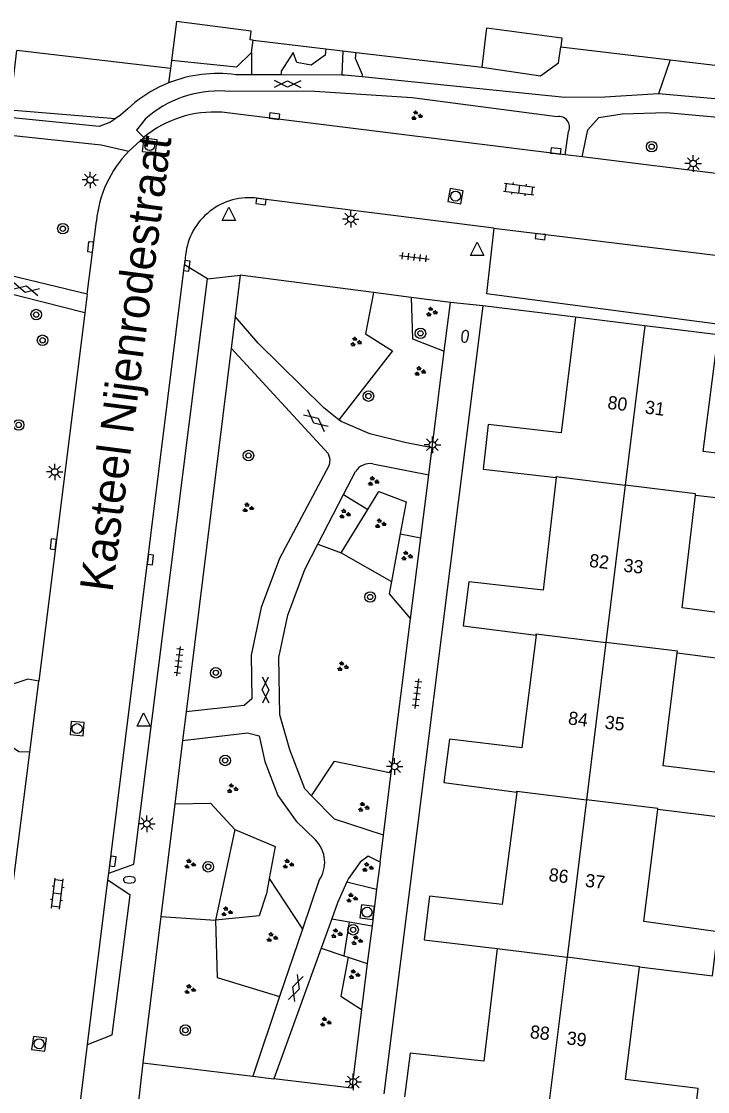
# Model space of a CAD drawing. Extents: x 131000 to 133014, y 396499 to 399001.
# Drawn here: x 131362.8 to 131414.8, y 396865 to 396946.2 of the extents above; entities that cross this region are included whole.
import ezdxf

# ---------------------------------------------------------------- set-up
doc = ezdxf.new("R2010")
doc.units = 0
for name, color, linetype in [('gg-afsc-erfafscheiding', 7, 'Continuous'), ('gg-afsc-muur', 7, 'Continuous'), ('gg-anno-huisnummerreeks BGT', 7, 'Continuous'), ('gg-anno-openbare ruimte label', 7, 'Continuous'), ('gg-bbg-hoofdgebouw', 7, 'Continuous'), ('gg-bbg-tussenscheiding', 7, 'Continuous'), ('gg-knt-verharding', 7, 'Continuous'), ('gg-knt-verharding nz', 7, 'Continuous'), ('gt-grn-groengrens', 7, 'Continuous'), ('gt-grn-weggrens', 7, 'Continuous'), ('gt-symb-boom', 7, 'Continuous'), ('gt-symb-brandkraan', 7, 'Continuous'), ('gt-symb-gesloten verharding', 7, 'Continuous'), ('gt-symb-groenvak', 7, 'Continuous'), ('gt-symb-klinker verharding', 7, 'Continuous'), ('gt-symb-kolk', 7, 'Continuous'), ('gt-symb-lichtmast', 7, 'Continuous'), ('gt-symb-rioolschacht', 7, 'Continuous'), ('gt-symb-tegel verharding', 7, 'Continuous'), ('gt-symb-waterafsluiter', 7, 'Continuous')]:
    doc.layers.add(name, color=color, linetype=linetype)

# ---------------------------------------------------------------- blocks, each defined once
blk = doc.blocks.new('gt0-GRVAK')
at = {"layer": 'gt-symb-groenvak'}
for p, q in [((-0.11, 0.189), (-0.228, 0.24)), ((-0.182, 0.153), (0.088, 0.153)), ((-0.091, 0.211), (-0.156, 0.322)), ((-0.047, 0.214), (-0.047, 0.393)), ((-0.004, 0.211), (0.061, 0.322)), ((0.015, 0.189), (0.133, 0.24)), ((0.262, -0.052), (0.197, 0.059)), ((0.305, -0.049), (0.305, 0.13)), ((0.349, -0.052), (0.414, 0.059)), ((-0.245, -0.228), (-0.363, -0.177)), ((-0.318, -0.264), (-0.047, -0.264)), ((-0.226, -0.206), (-0.291, -0.095)), ((-0.183, -0.203), (-0.183, -0.024)), ((-0.139, -0.206), (-0.074, -0.095)), ((-0.12, -0.228), (-0.002, -0.177)), ((0.243, -0.074), (0.125, -0.023)), ((0.17, -0.11), (0.441, -0.11)), ((0.368, -0.074), (0.486, -0.023))]:
    blk.add_line(p, q, dxfattribs=at)
blk = doc.blocks.new('gt0-BOOM')
at = {"layer": 'gt-symb-boom'}
for radius in [0.4, 0.2]:
    blk.add_circle((0, 0), radius, dxfattribs=at)
blk = doc.blocks.new('gt0-RS')
at = {"layer": 'gt-symb-rioolschacht'}
blk.add_lwpolyline([(-0.5, -0.5), (0.5, -0.5), (0.5, 0.5), (-0.5, 0.5)], close=True, dxfattribs=at)
blk.add_circle((0, 0), 0.375, dxfattribs=at)
blk = doc.blocks.new('gt0-LMAST')
at = {"layer": 'gt-symb-lichtmast'}
for p, q in [((-0.182, 0.173), (-0.447, 0.438)), ((-0.005, 0.246), (-0.005, 0.621)), ((0.172, 0.173), (0.437, 0.438)), ((-0.255, -0.004), (-0.63, -0.004)), ((-0.182, -0.181), (-0.447, -0.446)), ((-0.005, -0.254), (-0.005, -0.629)), ((0.437, -0.446), (0.172, -0.181)), ((0.245, -0.004), (0.62, -0.004))]:
    blk.add_line(p, q, dxfattribs=at)
blk.add_circle((-0.005, -0.004), 0.25, dxfattribs=at)
blk = doc.blocks.new('gt0-GESVH1')
at = {"layer": 'gt-symb-gesloten verharding'}
for p, q in [((-0.992, -0.261), (0.008, 0.239)), ((0.008, -0.261), (-0.992, 0.239)), ((0.008, 0.239), (1.008, -0.261)), ((1.008, 0.239), (0.008, -0.261))]:
    blk.add_line(p, q, dxfattribs=at)
blk = doc.blocks.new('gt0-KL1')
at = {"layer": 'gt-symb-klinker verharding'}
for p, q in [((-1.15, 0.3), (1.15, 0.3)), ((-1, -0.3), (-1, 0.3)), ((-0.5, 0.3), (-0.5, 0.45)), ((0, -0.3), (0, 0.3)), ((0.5, 0.3), (0.5, 0.45)), ((1, -0.3), (1, 0.3)), ((-1.15, -0.3), (1.15, -0.3)), ((-0.5, -0.45), (-0.5, -0.3)), ((0.5, -0.45), (0.5, -0.3))]:
    blk.add_line(p, q, dxfattribs=at)
blk = doc.blocks.new('gt0-KOLK')
at = {"layer": 'gt-symb-kolk'}
blk.add_lwpolyline([(0, 0), (0.375, 0), (0.375, 0.4), (-0.375, 0.4), (-0.375, 0), (0, 0)], dxfattribs=at)
blk = doc.blocks.new('gt0-BR')
at = {"layer": 'gt-symb-brandkraan'}
for centre, radius, start, end in [((-0.244, 0), 0.206, 107.56694, 252.43307), ((0.599, -2.664), 3, 106.89205, 107.56694), ((0, -0.691), 0.938, 73.10799, 106.89205), ((-0.599, -2.664), 3, 72.43309, 73.10799), ((0.244, 0), 0.206, 287.56695, 72.43309), ((0.599, 2.664), 3, 252.43307, 253.10797), ((0, 0.691), 0.938, 253.10797, 286.89206), ((-0.599, 2.664), 3, 286.89206, 287.56695)]:
    blk.add_arc(centre, radius, start, end, dxfattribs=at)
blk = doc.blocks.new('gt0-TEG1')
at = {"layer": 'gt-symb-tegel verharding'}
for p, q in [((-1.125, 0), (1.125, 0)), ((-0.9, -0.25), (-0.9, 0.25)), ((-0.45, -0.25), (-0.45, 0.25)), ((0, -0.25), (0, 0.25)), ((0.45, -0.25), (0.45, 0.25)), ((0.9, -0.25), (0.9, 0.25))]:
    blk.add_line(p, q, dxfattribs=at)
blk = doc.blocks.new('gt0-WAFSL')
at = {"layer": 'gt-symb-waterafsluiter'}
for p, q in [((-0.5, -0.333), (0, 0.667)), ((0, 0.667), (0.5, -0.333)), ((0.5, -0.333), (-0.5, -0.333))]:
    blk.add_line(p, q, dxfattribs=at)

msp = doc.modelspace()

# ---------------------------------------------------------------- linework, layer by layer
at = {"layer": 'gg-afsc-erfafscheiding'}
msp.add_line((131397.74, 396924.6), (131390.25, 396864.87), dxfattribs=at)
at = {"layer": 'gg-afsc-muur'}
for p, q in [((131380.233, 396943.794), (131380.344, 396944.733)), ((131404.77, 396923.73), (131397.74, 396924.6))]:
    msp.add_line(p, q, dxfattribs=at)
msp.add_lwpolyline([(131380.233, 396943.794), (131379.075, 396942.691), (131374.161, 396943.192)], dxfattribs=at)
at = {"layer": 'gg-bbg-hoofdgebouw'}
for p, q in [((131380.344, 396944.733), (131385.865, 396944.076)), ((131403.65, 396944.22), (131411.945, 396943.227)), ((131374.08, 396942.58), (131362.444, 396943.935)), ((131385.865, 396944.076), (131387.143, 396943.924)), ((131387.143, 396943.924), (131388.152, 396943.804)), ((131388.152, 396943.804), (131397.69, 396942.67)), ((131374.161, 396943.192), (131374.08, 396942.58)), ((131411.945, 396943.227), (131434.011, 396940.586)), ((131410.02, 396923.079), (131404.77, 396923.73)), ((131415.57, 396922.39), (131410.02, 396923.079))]:
    msp.add_line(p, q, dxfattribs=at)
for points in [[(131380.344, 396944.733), (131380.12, 396944.76), (131380.2, 396945.42), (131374.55, 396946.15), (131374.161, 396943.192)], [(131397.69, 396942.67), (131398.04, 396945.66), (131403.74, 396944.91), (131403.65, 396944.22)], [(131404.77, 396923.73), (131403.67, 396914.96), (131398.14, 396915.59), (131397.76, 396912.22), (131403.29, 396911.59)], [(131413.85, 396910.25), (131419.61, 396909.58), (131419.99, 396912.88), (131414.43, 396913.55), (131415.57, 396922.39)], [(131403.29, 396911.59), (131402.32, 396903.05), (131396.68, 396903.67), (131396.26, 396900.34), (131401.78, 396899.63)], [(131412.47, 396898.29), (131419.498, 396897.396), (131419.948, 396900.756), (131412.85, 396901.71), (131413.85, 396910.25)], [(131401.78, 396899.63), (131400.69, 396891.1), (131395.22, 396891.76), (131394.8, 396888.46), (131400.32, 396887.74)], [(131411, 396886.45), (131417.961, 396885.591), (131418.371, 396888.871), (131411.4, 396889.73), (131412.47, 396898.29)], [(131400.32, 396887.74), (131399.21, 396879.22), (131393.7, 396879.86), (131393.3, 396876.55), (131398.84, 396875.89)], [(131409.6, 396874.5), (131415.13, 396873.81), (131415.54, 396877.16), (131409.94, 396877.92), (131411, 396886.45)], [(131398.84, 396875.89), (131397.82, 396867.35), (131392.25, 396867.95), (131391.81, 396864.65)], [(131413.67, 396861.96), (131414.06, 396865.28), (131408.54, 396865.96), (131409.6, 396874.5)]]:
    msp.add_lwpolyline(points, dxfattribs=at)
at = {"layer": 'gg-bbg-tussenscheiding'}
for p, q in [((131410.02, 396923.079), (131408.531, 396911.003)), ((131408.531, 396911.003), (131407.061, 396899.082)), ((131407.061, 396899.082), (131405.591, 396887.161)), ((131405.591, 396887.161), (131404.122, 396875.241)), ((131398.84, 396875.89), (131404.122, 396875.241)), ((131404.122, 396875.241), (131402.651, 396863.316)), ((131409.6, 396874.5), (131404.122, 396875.241))]:
    msp.add_line(p, q, dxfattribs=at)
for points in [[(131403.29, 396911.59), (131403.297, 396911.652), (131408.531, 396911.003)], [(131413.85, 396910.25), (131413.861, 396910.343), (131408.531, 396911.003)], [(131401.78, 396899.63), (131401.794, 396899.738), (131407.061, 396899.082)], [(131412.47, 396898.29), (131412.485, 396898.41), (131407.061, 396899.082)], [(131400.32, 396887.74), (131400.33, 396887.818), (131405.591, 396887.161)], [(131411, 396886.45), (131411.005, 396886.491), (131405.591, 396887.161)]]:
    msp.add_lwpolyline(points, dxfattribs=at)
at = {"layer": 'gg-knt-verharding'}
for p, q in [((131380.226, 396942.101), (131379.032, 396942.105)), ((131382.464, 396942.092), (131380.226, 396942.101)), ((131387.072, 396942.074), (131382.464, 396942.092)), ((131371.393, 396939.996), (131370.863, 396939.534)), ((131403.994, 396936.038), (131377.97, 396939.26)), ((131403.994, 396936.038), (131404.233, 396937.816)), ((131370.921, 396936.317), (131372.054, 396937.35)), ((131405.272, 396935.88), (131403.994, 396936.038)), ((131426.19, 396933.29), (131405.272, 396935.88)), ((131398.589, 396930.485), (131380.7, 396932.74)), ((131367.778, 396925.486), (131368.47, 396931.01)), ((131375.23, 396928.47), (131375.136, 396927.713)), ((131367.778, 396925.486), (131359.668, 396927.433)), ((131376.884, 396926.642), (131375.136, 396927.713)), ((131379.37, 396926.91), (131378.981, 396923.774)), ((131389.452, 396925.605), (131379.37, 396926.91)), ((131392.313, 396925.235), (131389.452, 396925.605)), ((131367.778, 396925.486), (131367.601, 396924.07)), ((131395.29, 396924.85), (131392.313, 396925.235)), ((131394.825, 396921.155), (131395.29, 396924.85)), ((131367.601, 396924.07), (131364.11, 396896.15)), ((131378.981, 396923.774), (131378.686, 396921.387)), ((131378.686, 396921.387), (131375.275, 396893.83)), ((131393.905, 396913.841), (131394.825, 396921.155)), ((131393.647, 396911.791), (131393.905, 396913.841)), ((131389.416, 396912.609), (131393.647, 396911.791)), ((131387.202, 396910.296), (131388.104, 396912.045)), ((131393.046, 396907.009), (131393.647, 396911.791)), ((131385.259, 396906.527), (131387.202, 396910.296)), ((131392.274, 396900.862), (131393.046, 396907.009)), ((131390.808, 396889.195), (131392.274, 396900.862)), ((131363.43, 396890.77), (131364.11, 396896.15)), ((131375.275, 396893.83), (131375.005, 396891.647)), ((131375.005, 396891.647), (131374.412, 396886.855)), ((131362.09, 396880.2), (131363.43, 396890.77)), ((131390.214, 396884.464), (131390.808, 396889.195)), ((131374.412, 396886.855), (131373.354, 396878.307)), ((131389.957, 396882.417), (131390.214, 396884.464)), ((131389.957, 396882.417), (131389.702, 396880.387)), ((131369.342, 396881.053), (131369.409, 396881.599)), ((131385.321, 396881.025), (131384.082, 396877.36)), ((131389.702, 396880.387), (131389.353, 396877.601)), ((131373.354, 396878.307), (131371.98, 396867.21)), ((131386.297, 396878.141), (131385.492, 396875.911)), ((131384.082, 396877.36), (131382.352, 396872.24)), ((131389.353, 396877.601), (131388.994, 396874.744)), ((131385.492, 396875.911), (131381.917, 396866.016)), ((131388.994, 396874.744), (131388.557, 396871.26)), ((131382.352, 396872.24), (131380.314, 396866.209)), ((131367.182, 396863.652), (131367.798, 396868.619)), ((131371.98, 396867.21), (131380.314, 396866.209)), ((131380.314, 396866.209), (131381.917, 396866.016))]:
    msp.add_line(p, q, dxfattribs=at)
for points in [[(131388.609, 396941.937), (131387.274, 396942.073), (131387.072, 396942.074)], [(131411.056, 396940.651), (131406.99, 396940.417), (131403.963, 396940.371), (131388.609, 396941.937)], [(131369.895, 396938.757), (131369.539, 396938.506), (131368.672, 396938.178), (131353.225, 396939.729), (131352.687, 396940.084), (131352.853, 396941.597)], [(131403.371, 396938.924), (131392.404, 396940.363), (131385.022, 396940.826), (131378.208, 396940.867)], [(131434.85, 396935.52), (131432.32, 396936.8), (131429.42, 396937.84), (131426.61, 396939.02), (131416.488, 396940.17), (131411.056, 396940.651)], [(131370.863, 396939.534), (131370.297, 396939.041), (131369.895, 396938.757)], [(131372.174, 396938.751), (131371.517, 396937.895), (131372.054, 396937.35)], [(131405.272, 396935.88), (131405.693, 396937.924), (131406.529, 396938.865), (131408.295, 396939.153), (131411.669, 396939.237), (131418.309, 396938.638), (131427.28, 396937.29), (131429.46, 396936.29)], [(131354.124, 396938.36), (131368.833, 396936.794), (131370.921, 396936.317)], [(131398.589, 396930.485), (131398.034, 396925.522), (131422.031, 396922.362)], [(131369.409, 396881.599), (131371.301, 396882.265), (131376.884, 396926.642)], [(131367.601, 396924.07), (131359.423, 396926.139), (131358.724, 396925.796), (131358.24, 396925.233), (131357.965, 396923.398), (131358.063, 396921.848), (131358.695, 396919.777), (131359.499, 396917.976)], [(131386.843, 396915.958), (131385.707, 396916.873), (131380.732, 396921.773), (131378.981, 396923.774)], [(131378.686, 396921.387), (131386.036, 396913.406), (131386.144, 396912.977), (131386.099, 396912.505), (131382.341, 396905.449), (131380.958, 396901.732), (131380.192, 396898.121), (131380.258, 396894.817), (131379.674, 396894.308), (131375.275, 396893.83)], [(131393.905, 396913.841), (131391.848, 396914.238), (131389.176, 396914.895), (131387.002, 396915.83), (131386.843, 396915.958)], [(131384.761, 396887.468), (131384.269, 396887.976), (131383.129, 396890.945), (131382.366, 396893.583), (131382.298, 396897.93), (131382.98, 396901.145), (131384.265, 396904.599), (131385.259, 396906.527)], [(131364.11, 396896.15), (131363.27, 396896.3), (131361.39, 396895.67), (131352.1, 396896.827)], [(131363.43, 396890.77), (131362.61, 396890.8), (131361.16, 396891.78)], [(131375.005, 396891.647), (131379.919, 396892.223), (131380.8, 396892.005), (131381.241, 396890.063), (131382.213, 396887.488), (131383.598, 396885.531), (131385.073, 396884.11)], [(131390.214, 396884.464), (131386.497, 396885.676), (131384.761, 396887.468)], [(131389.957, 396882.417), (131389.051, 396882.878), (131388.453, 396882.433), (131387.57, 396881.195), (131387.452, 396880.935)], [(131367.798, 396868.619), (131369.68, 396869.343), (131371.027, 396879.917), (131369.342, 396881.053)], [(131387.452, 396880.935), (131386.731, 396879.341), (131386.297, 396878.141)], [(131388.557, 396871.26), (131387.81, 396865.31), (131381.917, 396866.016)]]:
    msp.add_lwpolyline(points, dxfattribs=at)
for centre, radius, start, end in [((131377.651, 396932.222), 9.979, 82.04276, 111.85288), ((131377.65, 396932.219), 9.982, 111.84641, 128.82044), ((131377.774, 396932.443), 8.435, 87.05183, 131.59762), ((131377.384, 396930.956), 8.324, 85.9666, 129.81909), ((131403.526, 396938.155), 0.784, 334.34494, 101.41934), ((131377.318, 396930.143), 8.891, 136.01752, 174.40345), ((131380.05, 396927.934), 4.85, 82.29884, 173.65389), ((131389.174, 396911.363), 1.269, 79.02227, 147.50135), ((131383.366, 396882.42), 2.402, 324.49146, 44.70067)]:
    msp.add_arc(centre, radius, start, end, dxfattribs=at)
at = {"layer": 'gg-knt-verharding nz'}
for p, q in [((131398.589, 396930.485), (131422.755, 396927.538)), ((131369.409, 396881.599), (131375.136, 396927.713)), ((131367.798, 396868.619), (131369.342, 396881.053))]:
    msp.add_line(p, q, dxfattribs=at)
at = {"layer": 'gt-grn-groengrens'}
for p, q in [((131380.233, 396943.794), (131380.226, 396942.101)), ((131387.143, 396943.924), (131387.072, 396942.074)), ((131411.945, 396943.227), (131411.056, 396940.651)), ((131374.08, 396942.58), (131373.936, 396941.484)), ((131387.202, 396910.296), (131389.041, 396909.165)), ((131387.025, 396905.865), (131389.041, 396909.165)), ((131391.487, 396907.302), (131390.822, 396903.713)), ((131391.487, 396907.302), (131393.046, 396907.009)), ((131385.259, 396906.527), (131387.025, 396905.865)), ((131387.025, 396905.865), (131390.822, 396903.713)), ((131378.956, 396884.901), (131377.504, 396878.034)), ((131381.57, 396881.181), (131384.082, 396877.36)), ((131387.452, 396880.935), (131389.702, 396880.387)), ((131373.354, 396878.307), (131377.504, 396878.034)), ((131386.297, 396878.141), (131387.627, 396877.906)), ((131387.627, 396877.906), (131387.21, 396875.338)), ((131387.627, 396877.906), (131389.353, 396877.601)), ((131385.492, 396875.911), (131387.21, 396875.338)), ((131387.21, 396875.338), (131387.547, 396875.226)), ((131387.547, 396875.226), (131388.994, 396874.744))]:
    msp.add_line(p, q, dxfattribs=at)
for points in [[(131397.69, 396942.67), (131402.106, 396942.029), (131403.486, 396943.002), (131403.65, 396944.22)], [(131369.895, 396938.757), (131361.918, 396939.42), (131362.444, 396943.935)], [(131385.865, 396944.076), (131385.806, 396943.58), (131384.746, 396942.835), (131383.646, 396943.044), (131383.385, 396943.792), (131382.465, 396942.37), (131382.464, 396942.092)], [(131388.609, 396941.937), (131388.627, 396942.113), (131388.097, 396943.341), (131388.152, 396943.804)], [(131389.452, 396925.605), (131388.849, 396922.481), (131390.895, 396921.179), (131386.843, 396915.958)], [(131392.313, 396925.235), (131392.423, 396922.089), (131394.825, 396921.155)], [(131389.041, 396909.165), (131389.87, 396910.521), (131391.939, 396909.745), (131391.487, 396907.302)], [(131390.822, 396903.713), (131390.646, 396902.762), (131392.274, 396900.862)], [(131384.761, 396887.468), (131386.508, 396890.088), (131390.808, 396889.195)], [(131374.412, 396886.855), (131377.113, 396886.911), (131378.956, 396884.901)], [(131378.956, 396884.901), (131382.027, 396883.617), (131381.57, 396881.181)], [(131381.57, 396881.181), (131381.357, 396880.044), (131380.798, 396878.369), (131377.504, 396878.034)], [(131377.504, 396878.034), (131377.616, 396873.679), (131382.352, 396872.24)], [(131387.547, 396875.226), (131386.996, 396872.283), (131388.557, 396871.26)]]:
    msp.add_lwpolyline(points, dxfattribs=at)
at = {"layer": 'gt-grn-weggrens'}
for p, q in [((131376.884, 396926.642), (131379.37, 396926.91)), ((131397.74, 396924.6), (131395.29, 396924.85)), ((131371.98, 396867.21), (131371.64, 396864.1))]:
    msp.add_line(p, q, dxfattribs=at)

# ---------------------------------------------------------------- block references
at = {"layer": 'gt-symb-boom'}
for p in [(131410.535, 396936.656), (131365.935, 396930.439), (131363.916, 396923.928), (131364.398, 396921.983), (131393.019, 396922.507), (131389.078, 396917.753), (131362.587, 396915.564), (131379.992, 396913.247), (131389.208, 396902.524), (131377.518, 396896.781), (131378.227, 396890.139), (131376.948, 396882.083), (131387.919, 396877.305), (131375.213, 396869.694)]:
    msp.add_blockref('gt0-BOOM', p, dxfattribs=at)
at = {"layer": 'gt-symb-brandkraan', "rotation": 80.6789392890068}
msp.add_blockref('gt0-BR', (131396.4, 396922.285), dxfattribs=at)
at = {"layer": 'gt-symb-brandkraan'}
msp.add_blockref('gt0-BR', (131370.978, 396881.092), dxfattribs=at)
at = {"layer": 'gt-symb-gesloten verharding'}
for p, rotation in [((131382.962, 396941.394), 179.7708181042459), ((131363.125, 396925.872), -13.48012621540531), ((131385.103, 396915.909), -39.196688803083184), ((131381.277, 396895.474), 90.9166542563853), ((131383.574, 396872.887), 71.3294165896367)]:
    msp.add_blockref('gt0-GESVH1', p, dxfattribs=dict(at, rotation=rotation))
at = {"layer": 'gt-symb-groenvak'}
for p in [(131392.72, 396939.005), (131393.85, 396924.127), (131388.104, 396921.855), (131392.962, 396919.626), (131389.428, 396911.289), (131379.934, 396909.285), (131387.27, 396908.813), (131389.967, 396908.082), (131391.966, 396905.638), (131387.111, 396897.253), (131378.757, 396888.004), (131388.685, 396886.592), (131375.536, 396882.281), (131382.977, 396882.281), (131389.004, 396882.033), (131387.805, 396879.7), (131378.333, 396878.668), (131381.755, 396876.725), (131386.645, 396877.015), (131388.186, 396876.489), (131387.987, 396873.913), (131375.536, 396872.78), (131385.805, 396870.302)]:
    msp.add_blockref('gt0-GRVAK', p, dxfattribs=at)
at = {"layer": 'gt-symb-klinker verharding'}
for p, rotation in [((131400.5, 396933.438), -7.125016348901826), ((131365.516, 396880.05), 82.8749836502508)]:
    msp.add_blockref('gt0-KL1', p, dxfattribs=dict(at, rotation=rotation))
at = {"layer": 'gt-symb-kolk'}
for p, rotation in [((131381.938, 396938.77), -7.068140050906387), ((131403.249, 396936.13), -7.068140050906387), ((131380.973, 396932.698), 171.3757712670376), ((131402.128, 396930.036), 172.87498364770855), ((131368.223, 396929.037), 84.20389934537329), ((131375.128, 396927.654), -97.23872650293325), ((131365.404, 396906.502), 82.80691860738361), ((131372.362, 396905.376), -97.29556014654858), ((131369.519, 396882.518), -97.46597406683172)]:
    msp.add_blockref('gt0-KOLK', p, dxfattribs=dict(at, rotation=rotation))
at = {"layer": 'gt-symb-lichtmast'}
for p in [(131413.685, 396935.379), (131368.019, 396934.137), (131387.743, 396931.171), (131393.932, 396914.068), (131365.318, 396912.006), (131391.071, 396889.679), (131372.307, 396885.339), (131387.938, 396865.779)]:
    msp.add_blockref('gt0-LMAST', p, dxfattribs=at)
at = {"layer": 'gt-symb-rioolschacht'}
for p, rotation in [((131372.506, 396936.735), 82.87498365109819), ((131395.68, 396932.907), -9.556527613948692), ((131367.015, 396892.554), 85.1221191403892), ((131388.978, 396878.638), -7.004259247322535), ((131364.133, 396868.664), 82.00768607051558)]:
    msp.add_blockref('gt0-RS', p, dxfattribs=dict(at, rotation=rotation))
at = {"layer": 'gt-symb-tegel verharding'}
for p, rotation in [((131392.555, 396928.279), -7.125016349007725), ((131374.716, 396897.664), 82.99574075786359), ((131392.758, 396895.201), 82.99574075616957)]:
    msp.add_blockref('gt0-TEG1', p, dxfattribs=dict(at, rotation=rotation))
at = {"layer": 'gt-symb-waterafsluiter'}
for p in [(131378.508, 396931.405), (131397.322, 396928.75), (131372.052, 396893.069)]:
    msp.add_blockref('gt0-WAFSL', p, dxfattribs=at)

# ---------------------------------------------------------------- texts
at = {"layer": 'gg-anno-huisnummerreeks BGT'}
for s, rotation, p in [('80', 352.9, (131407.149, 396916.796)), ('31', 352.6, (131409.987, 396916.44)), ('82', 353.5, (131405.764, 396904.811)), ('33', 353.3, (131408.362, 396904.455)), ('84', 352.7, (131404.166, 396892.877)), ('35', 352.9, (131406.94, 396892.562)), ('86', 352.6, (131402.695, 396881.012)), ('37', 352.9, (131405.455, 396880.57)), ('88', 353.2, (131401.276, 396869.1)), ('39', 352.9, (131404.057, 396868.629))]:
    msp.add_text(s, height=1, rotation=rotation, dxfattribs=at).set_placement(p)
at = {"layer": 'gg-anno-openbare ruimte label'}
msp.add_text('Kasteel Nijenrodestraat', height=2.5, rotation=82.6, dxfattribs=at).set_placement((131369.684, 396902.839))

doc.saveas('drawing.dxf')
